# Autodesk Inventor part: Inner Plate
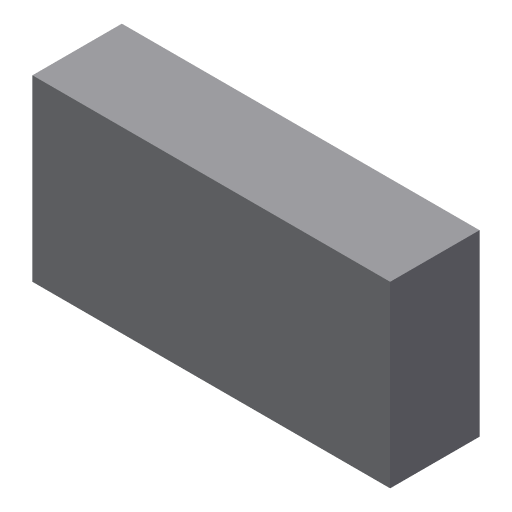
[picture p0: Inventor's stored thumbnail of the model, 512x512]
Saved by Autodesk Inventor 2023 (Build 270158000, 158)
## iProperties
Created: 2010-04
Part Number: Inner Plate
Document SubType Name: Modeling
Designer: CADSoft
Density: 1 g/cm^3
Material: Generic
Appearance: Default
Author: CADSoft
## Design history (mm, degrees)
sketch "Sketch1"
  geometry: L1 (-20.23, -7.511)-(19.77, -7.511); L2 (19.77, -7.511)-(19.77, 12.489); L3 (19.77, 12.489)-(-20.23, 12.489); L4 (-20.23, 12.489)-(-20.23, -7.511); 1 further point
  constraints: 8 end point, 2 parallel, 1 horizontal, 1 perpendicular
workplane "Work Plane1"
extrude "Extrusion1" new body sketch "Sketch1" stored distance "d0" = 25.4; taper "d1" = 0 deg
body "Solid1"
